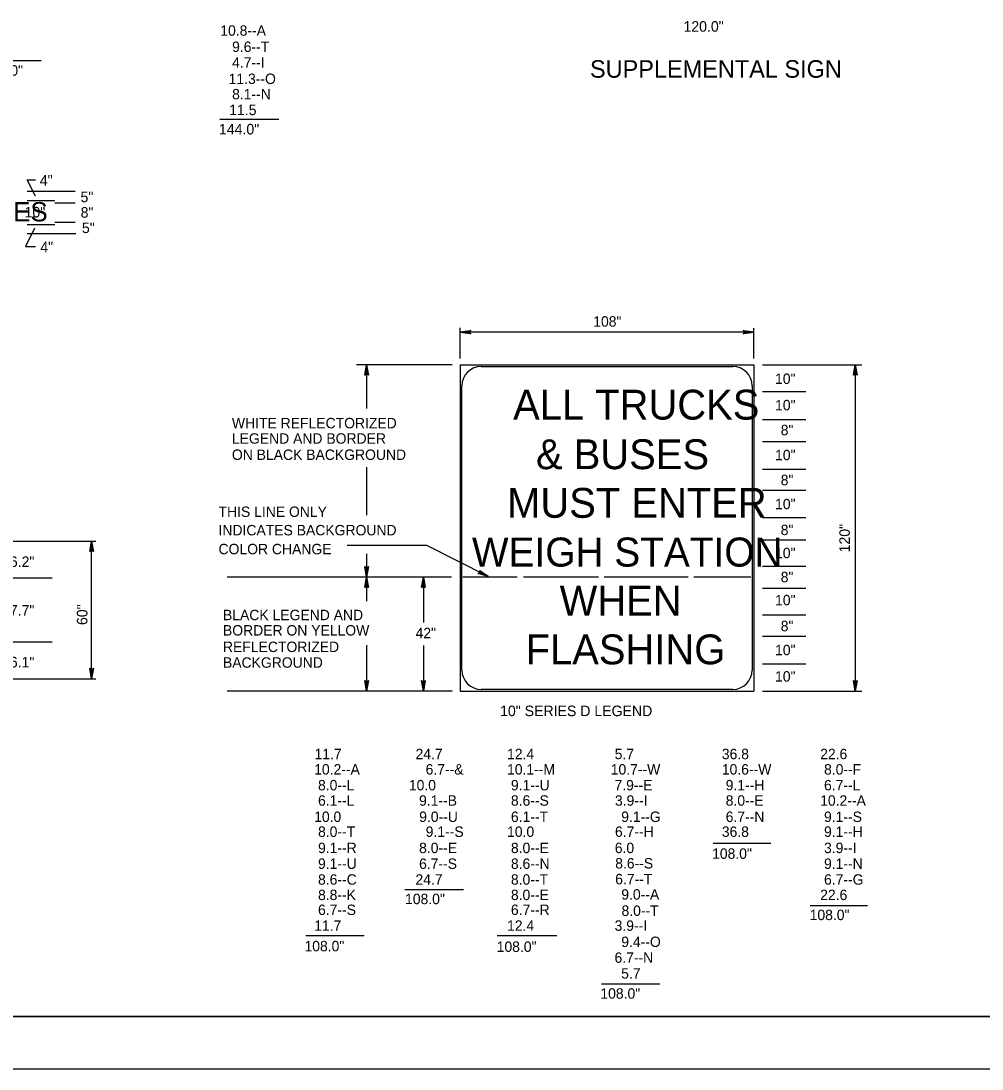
# Model space of a CAD drawing. Extents: x 649604 to 650509, y 298458 to 299646.
# Drawn here: x 649933.2 to 650206.9, y 298457.6 to 298756.1 of the extents above; entities that cross this region are included whole.
import ezdxf

# ---------------------------------------------------------------- set-up
doc = ezdxf.new("R2010")
doc.units = 0
for name, color, linetype in [('1', 7, 'Continuous'), ('2', 7, 'Continuous'), ('3', 7, 'Continuous'), ('PLT-BNDY', 7, 'Continuous')]:
    doc.layers.add(name, color=color, linetype=linetype)

# ---------------------------------------------------------------- blocks, each defined once
blk = doc.blocks.new('RARROW')
at = {"layer": '3'}
blk.add_lwpolyline([(-2.2695, 0.285), (-2.184875, 0.12075), (0, 0), (-2.2695, 0.285), (-2.38575, 0.384625), (0, 0), (-2.183125, -0.108), (-2.262875, -0.2705), (0, 0), (-2.38575, -0.379125), (-2.262875, -0.2705)], dxfattribs=at)

msp = doc.modelspace()

# ---------------------------------------------------------------- linework, layer by layer
at = {"layer": '1'}
for p, q in [((650430.31, 298472.63), (649644.31, 298472.63)), ((649644.31, 298472.63), (650230.31, 298472.63))]:
    msp.add_line(p, q, dxfattribs=at)
at = {"layer": '2'}
for p, q in [((649922.15, 298744.93), (649938.95, 298744.93)), ((649989.85, 298728.2), (650006.65, 298728.2)), ((649937.38, 298706.29), (649934.99, 298710.86)), ((649934.99, 298710.86), (649937.38, 298710.86)), ((649934.95, 298707.68), (649948.69, 298707.68)), ((649934.95, 298705.01), (649942.83, 298705.01)), ((649942.83, 298704.35), (649948.69, 298704.35)), ((649937.1, 298697.16), (649934.5, 298691.89)), ((649934.95, 298698.18), (649942.83, 298698.18)), ((649942.83, 298698.85), (649948.69, 298698.85)), ((649934.95, 298695.6), (649948.81, 298695.6)), ((649934.5, 298691.89), (649937.31, 298691.89)), ((650058.27, 298660), (650058.27, 298668.75)), ((650141.89, 298667.5), (650058.27, 298667.5)), ((650141.89, 298660), (650141.89, 298668.63)), ((650056.02, 298658.25), (650028.77, 298658.25)), ((650031.64, 298658.25), (650031.64, 298645.75)), ((650058.27, 298658.25), (650141.89, 298658.25)), ((650058.27, 298658.25), (650058.27, 298565.25)), ((650141.89, 298658.25), (650141.89, 298565.25)), ((650144.39, 298658.25), (650172.64, 298658.25)), ((650170.76, 298658.25), (650170.76, 298565.25)), ((650064.27, 298657.75), (650135.89, 298657.75)), ((650058.77, 298571.25), (650058.77, 298652.25)), ((650141.39, 298652.25), (650141.39, 298571.25)), ((650144.39, 298650.63), (650156.66, 298650.63)), ((650144.39, 298642.63), (650156.66, 298642.63)), ((650144.39, 298636.38), (650156.66, 298636.38)), ((650031.64, 298629.06), (650031.64, 298615.38)), ((650144.39, 298628.5), (650156.66, 298628.5)), ((650144.39, 298622.5), (650156.66, 298622.5)), ((650144.39, 298614.75), (650156.66, 298614.75)), ((649927.06, 298608.01), (649954.58, 298608.01)), ((649953.33, 298568.76), (649953.33, 298608.01)), ((650144.39, 298608.38), (650156.66, 298608.38)), ((650048.77, 298606.75), (650026.11, 298606.75)), ((650031.64, 298604.38), (650031.64, 298597.75)), ((650066.27, 298597.88), (650048.77, 298606.75)), ((650144.39, 298600.88), (650156.66, 298600.88)), ((649927.06, 298597.51), (649942.12, 298597.51)), ((650055.8, 298597.75), (649991.89, 298597.75)), ((650031.64, 298597.75), (650031.64, 298590.88)), ((650047.8, 298597.75), (650047.8, 298584.77)), ((650074.52, 298597.75), (650059.02, 298597.75)), ((650097.64, 298597.75), (650076.27, 298597.75)), ((650123.14, 298597.75), (650099.27, 298597.75)), ((650141.02, 298597.75), (650124.77, 298597.75)), ((650144.39, 298594.63), (650156.66, 298594.63)), ((650144.39, 298587), (650156.66, 298587)), ((650144.39, 298580.88), (650156.66, 298580.88)), ((649927.06, 298579.26), (649942.12, 298579.26)), ((650031.64, 298578.38), (650031.64, 298565.25)), ((650047.8, 298578.25), (650047.8, 298565.25)), ((650144.39, 298573), (650156.66, 298573)), ((649927.06, 298568.76), (649954.58, 298568.76)), ((650135.89, 298565.75), (650064.27, 298565.75)), ((650056.02, 298565.25), (649991.89, 298565.25)), ((650058.27, 298565.25), (650141.89, 298565.25)), ((650144.39, 298565.25), (650172.64, 298565.25)), ((650130.28, 298522), (650146.76, 298522)), ((650042.55, 298508.72), (650059.19, 298508.72)), ((650157.91, 298504.25), (650174.23, 298504.25)), ((650014.34, 298495.63), (650030.98, 298495.63)), ((650068.79, 298495.63), (650085.76, 298495.63)), ((650098.48, 298481.88), (650115.12, 298481.88))]:
    msp.add_line(p, q, dxfattribs=at)
for centre, start, end in [((650064.27, 298652.25), 90, 180), ((650135.89, 298652.25), 0, 90), ((650064.27, 298571.25), 180, 270), ((650135.89, 298571.25), 270, 360)]:
    msp.add_arc(centre, 5.5, start, end, dxfattribs=at)
at = {"layer": 'PLT-BNDY'}
msp.add_lwpolyline([(649604.31, 299051.63), (650445.31, 299051.63), (650445.31, 298457.63), (649604.31, 298457.63)], close=True, dxfattribs=at)

# ---------------------------------------------------------------- block references
at = {"layer": '2', "xscale": 1.2574347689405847}
for p, yscale, rotation in [((650058.27, 298667.5), 1.3092961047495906, 180), ((650031.64, 298658.25), 1.3092961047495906, 89.99999999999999), ((650170.76, 298658.25), 1.3092961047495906, 89.99999999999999), ((649953.33, 298608.01), 1.3092961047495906, 89.99999999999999), ((650031.64, 298597.75), 1.3092961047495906, -90.00000000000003), ((650066.27, 298597.88), 1.3092961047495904, -26.538667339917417), ((650031.64, 298597.75), 1.3092961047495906, 89.99999999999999), ((650047.8, 298597.75), 1.3092961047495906, 89.99999999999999), ((649953.33, 298568.76), 1.3092961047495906, -90.00000000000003), ((650031.64, 298565.25), 1.3092961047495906, -90.00000000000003), ((650047.8, 298565.25), 1.3092961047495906, -90.00000000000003), ((650170.76, 298565.25), 1.3092961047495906, -90.00000000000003)]:
    msp.add_blockref('RARROW', p, dxfattribs=dict(at, yscale=yscale, rotation=rotation))
at = {"layer": '2', "xscale": 1.2574347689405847, "yscale": 1.3092961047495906}
msp.add_blockref('RARROW', (650141.89, 298667.5), dxfattribs=at)

# ---------------------------------------------------------------- texts
at = {"layer": '2'}
for s, height, p in [(' 10.8--A', 2.966, (649988.87, 298751.94)), ('120.0"   ', 3, (650121.85, 298753.09)), (' 9.6--T', 2.966, (649992.23, 298747.32)), (' 4.7--I', 2.966, (649992.23, 298742.82)), ('SUPPLEMENTAL SIGN', 5, (650095.23, 298739.98)), ('144.0"', 3, (649922.36, 298740.55)), ('11.3--O', 2.966, (649992.35, 298738.2)), (' 8.1--N', 2.966, (649992.23, 298733.82)), ('11.5', 3, (649992.48, 298729.32)), ('144.0"', 3, (649989.59, 298723.82)), ('4"', 3, (649938.59, 298709.23)), ('5"', 3, (649950.18, 298704.52)), ('NEXT REST AREA    MILES', 5.5, (649847.23, 298699.05)), ('10"', 3, (649934.25, 298700.18)), ('8"', 3, (649950.21, 298700.11)), ('5"', 3, (649950.58, 298695.73)), ('4"', 3, (649938.73, 298690.26)), ('108"', 2.966, (650096.16, 298669.08)), ('10"', 2.966, (650147.93, 298652.76)), ('10"', 2.966, (650147.93, 298645.25)), ('WHITE REFLECTORIZED', 2.9663, (649993.28, 298640.12)), ('8"', 2.966, (650149.54, 298638.14)), ('LEGEND AND BORDER', 2.9663, (649993.28, 298635.74)), ('ON BLACK BACKGROUND', 2.9663, (649993.28, 298631.12)), ('10"', 2.966, (650147.93, 298631.03)), ('8"', 2.966, (650149.54, 298623.92)), ('10"', 2.966, (650147.93, 298617.08)), ('THIS LINE ONLY', 2.9663, (649989.47, 298614.88)), ('INDICATES BACKGROUND', 2.9663, (649989.47, 298609.63)), ('8"', 2.966, (650149.54, 298609.7)), ('COLOR CHANGE', 2.9663, (649989.47, 298604.25)), ('10"', 2.966, (650147.93, 298603.13)), ('16.2"', 3, (649927.82, 298600.63)), ('8"', 2.966, (650149.54, 298596.28)), ('10"', 2.966, (650147.93, 298589.71)), ('27.7"', 3, (649927.82, 298586.76)), ('BLACK LEGEND AND', 2.9663, (649990.74, 298585.47)), ('BORDER ON YELLOW', 2.9663, (649990.74, 298581.1)), ('42"', 2.966, (650045.58, 298580.34)), ('8"', 2.966, (650149.54, 298582.33)), ('REFLECTORIZED ', 2.9663, (649990.74, 298576.4)), ('10"', 2.966, (650147.93, 298575.49)), ('16.1"', 3, (649927.82, 298572.01)), ('BACKGROUND', 2.966, (649990.74, 298571.93)), ('10"', 2.966, (650147.93, 298567.98)), (' 10" SERIES D LEGEND', 3, (650068.52, 298558.14)), ('11.7    ', 2.966, (650016.8, 298545.88)), ('24.7    ', 2.966, (650045.56, 298545.88)), ('12.4   ', 2.966, (650071.62, 298545.88)), (' 5.7', 2.966, (650101.16, 298545.88)), ('36.8   ', 2.966, (650132.77, 298545.88)), ('22.6   ', 2.966, (650160.77, 298545.88)), ('10.2--A', 2.966, (650016.7, 298541.5)), ('6.7--&', 2.966, (650048.44, 298541.5)), ('10.1--M', 2.966, (650071.62, 298541.5)), ('10.7--W', 2.966, (650101.14, 298541.5)), ('10.6--W', 2.966, (650132.77, 298541.5)), (' 8.0--F', 2.966, (650160.77, 298541.5)), (' 8.0--L', 2.966, (650016.7, 298537)), (' 10.0', 2.966, (650042.56, 298537)), (' 9.1--U', 2.966, (650071.62, 298537)), (' 7.9--E', 2.966, (650101.11, 298537)), (' 9.1--H', 2.966, (650132.77, 298537)), (' 6.7--L', 2.966, (650160.77, 298537)), (' 6.1--L', 2.966, (650016.7, 298532.63)), (' 9.1--B', 2.966, (650045.46, 298532.63)), (' 8.6--S', 2.966, (650071.62, 298532.63)), (' 3.9--I', 2.966, (650101.24, 298532.63)), (' 8.0--E', 2.966, (650132.77, 298532.63)), ('10.2--A', 2.966, (650160.77, 298532.63)), ('10.0   ', 2.966, (650016.7, 298528)), (' 9.0--U   ', 2.966, (650045.5, 298528)), (' 6.1--T', 2.966, (650071.62, 298528)), ('9.1--G', 2.966, (650104.12, 298528)), (' 6.7--N', 2.966, (650132.77, 298528)), (' 9.1--S', 2.966, (650160.77, 298528)), (' 8.0--T', 2.966, (650016.7, 298523.75)), ('9.1--S', 2.966, (650048.46, 298523.75)), ('10.0   ', 2.966, (650071.62, 298523.75)), (' 6.7--H', 2.966, (650101.24, 298523.75)), ('36.8   ', 2.966, (650132.77, 298523.75)), (' 9.1--H', 2.966, (650160.77, 298523.75)), (' 9.1--R', 2.966, (650016.7, 298519.13)), (' 8.0--E', 2.966, (650045.48, 298519.13)), (' 8.0--E', 2.966, (650071.62, 298519.13)), (' 6.0   ', 2.966, (650101.19, 298519.13)), (' 3.9--I', 2.966, (650160.77, 298519.13)), (' 9.1--U', 2.966, (650016.7, 298514.63)), (' 6.7--S', 2.966, (650045.47, 298514.63)), (' 8.6--N', 2.966, (650071.62, 298514.63)), (' 8.6--S', 2.966, (650101.31, 298514.75)), ('108.0"', 2.966, (650130, 298517.51)), (' 9.1--N', 2.966, (650160.77, 298514.63)), (' 8.6--C', 2.966, (650016.7, 298510.13)), ('24.7', 2.966, (650045.54, 298510.13)), (' 8.0--T', 2.966, (650071.62, 298510.13)), (' 6.7--T', 2.966, (650101.31, 298510.25)), (' 6.7--G', 2.966, (650160.77, 298510.13)), (' 8.8--K', 2.966, (650016.7, 298505.75)), (' 8.0--E', 2.966, (650071.62, 298505.75)), ('9.0--A', 2.966, (650104.15, 298505.88)), ('22.6   ', 2.966, (650160.77, 298505.75)), ('108.0" ', 2.966, (650042.58, 298504.59)), (' 6.7--S', 2.966, (650016.7, 298501.5)), (' 6.7--R', 2.966, (650071.62, 298501.5)), ('8.0--T', 2.966, (650104.21, 298501.25)), ('108.0"', 2.966, (650157.78, 298500.05)), ('11.7   ', 2.966, (650016.7, 298497)), ('12.4   ', 2.966, (650071.62, 298497)), (' 3.9--I', 2.966, (650101.14, 298497)), ('108.0" ', 2.966, (650013.95, 298491.16)), ('108.0"', 2.966, (650068.67, 298491)), ('9.4--O', 2.966, (650104.15, 298492.38)), (' 6.7--N', 2.966, (650101.12, 298487.88)), ('5.7   ', 2.966, (650104.11, 298483.38)), ('108.0"', 2.966, (650098.19, 298477.66))]:
    msp.add_text(s, height=height, dxfattribs=at).set_placement(p)
for s, height, rotation, p in [('ALL TRUCKS', 8.501, 360, (650073.34, 298642.61)), ('& BUSES', 8.501, 360, (650079.86, 298628.49)), ('MUST ENTER', 8.501, 360, (650071.64, 298614.64)), ('120"', 3, 90, (650169.22, 298604.78)), ('WEIGH STATION', 8.269, 360, (650061.61, 298600.74)), ('WHEN', 8.501, 360, (650086.59, 298586.8)), ('60"', 3, 90, (649952.14, 298584.1)), ('FLASHING', 8.501, 360, (650076.9, 298572.9))]:
    msp.add_text(s, height=height, rotation=rotation, dxfattribs=at).set_placement(p)

doc.saveas('drawing.dxf')
